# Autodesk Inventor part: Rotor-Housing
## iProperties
Shininess: 64.0
Length Units: 11269
Angle Units: 11279
Time Units: 11290
Mass Units: 11283
Length Display Precision: 3
Angle Display Precision: 2
Compacted: True
Part Number: Rotor-Housing
Document SubType Name: Modeling
Created: 2004-01
Designer: Administrator
Manufacturer: Standard
Standards Organization: Custom
Density: 1 g/cm^3
Density: 0.0
Volumn: 0.0
Area: 0.0
PropertySet Name: Model Information
Control State: 0
Master: False
Checked Out: False
Author: Administrator
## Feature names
1. Extrusion1
2. Hole1
3. Circular Pattern1
4. Mirror1
5. Hole2
6. Circular Pattern2
